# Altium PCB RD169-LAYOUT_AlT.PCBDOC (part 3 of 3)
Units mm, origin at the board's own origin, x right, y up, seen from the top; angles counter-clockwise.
Board outline 192 x 135 mm, 2 copper layers (TOP, BOTTOM), stack 0 mm thick; 266 components, 140 nets, 1304 pads, 0 vias.
Unrouted connection lines stored in the file: 1.
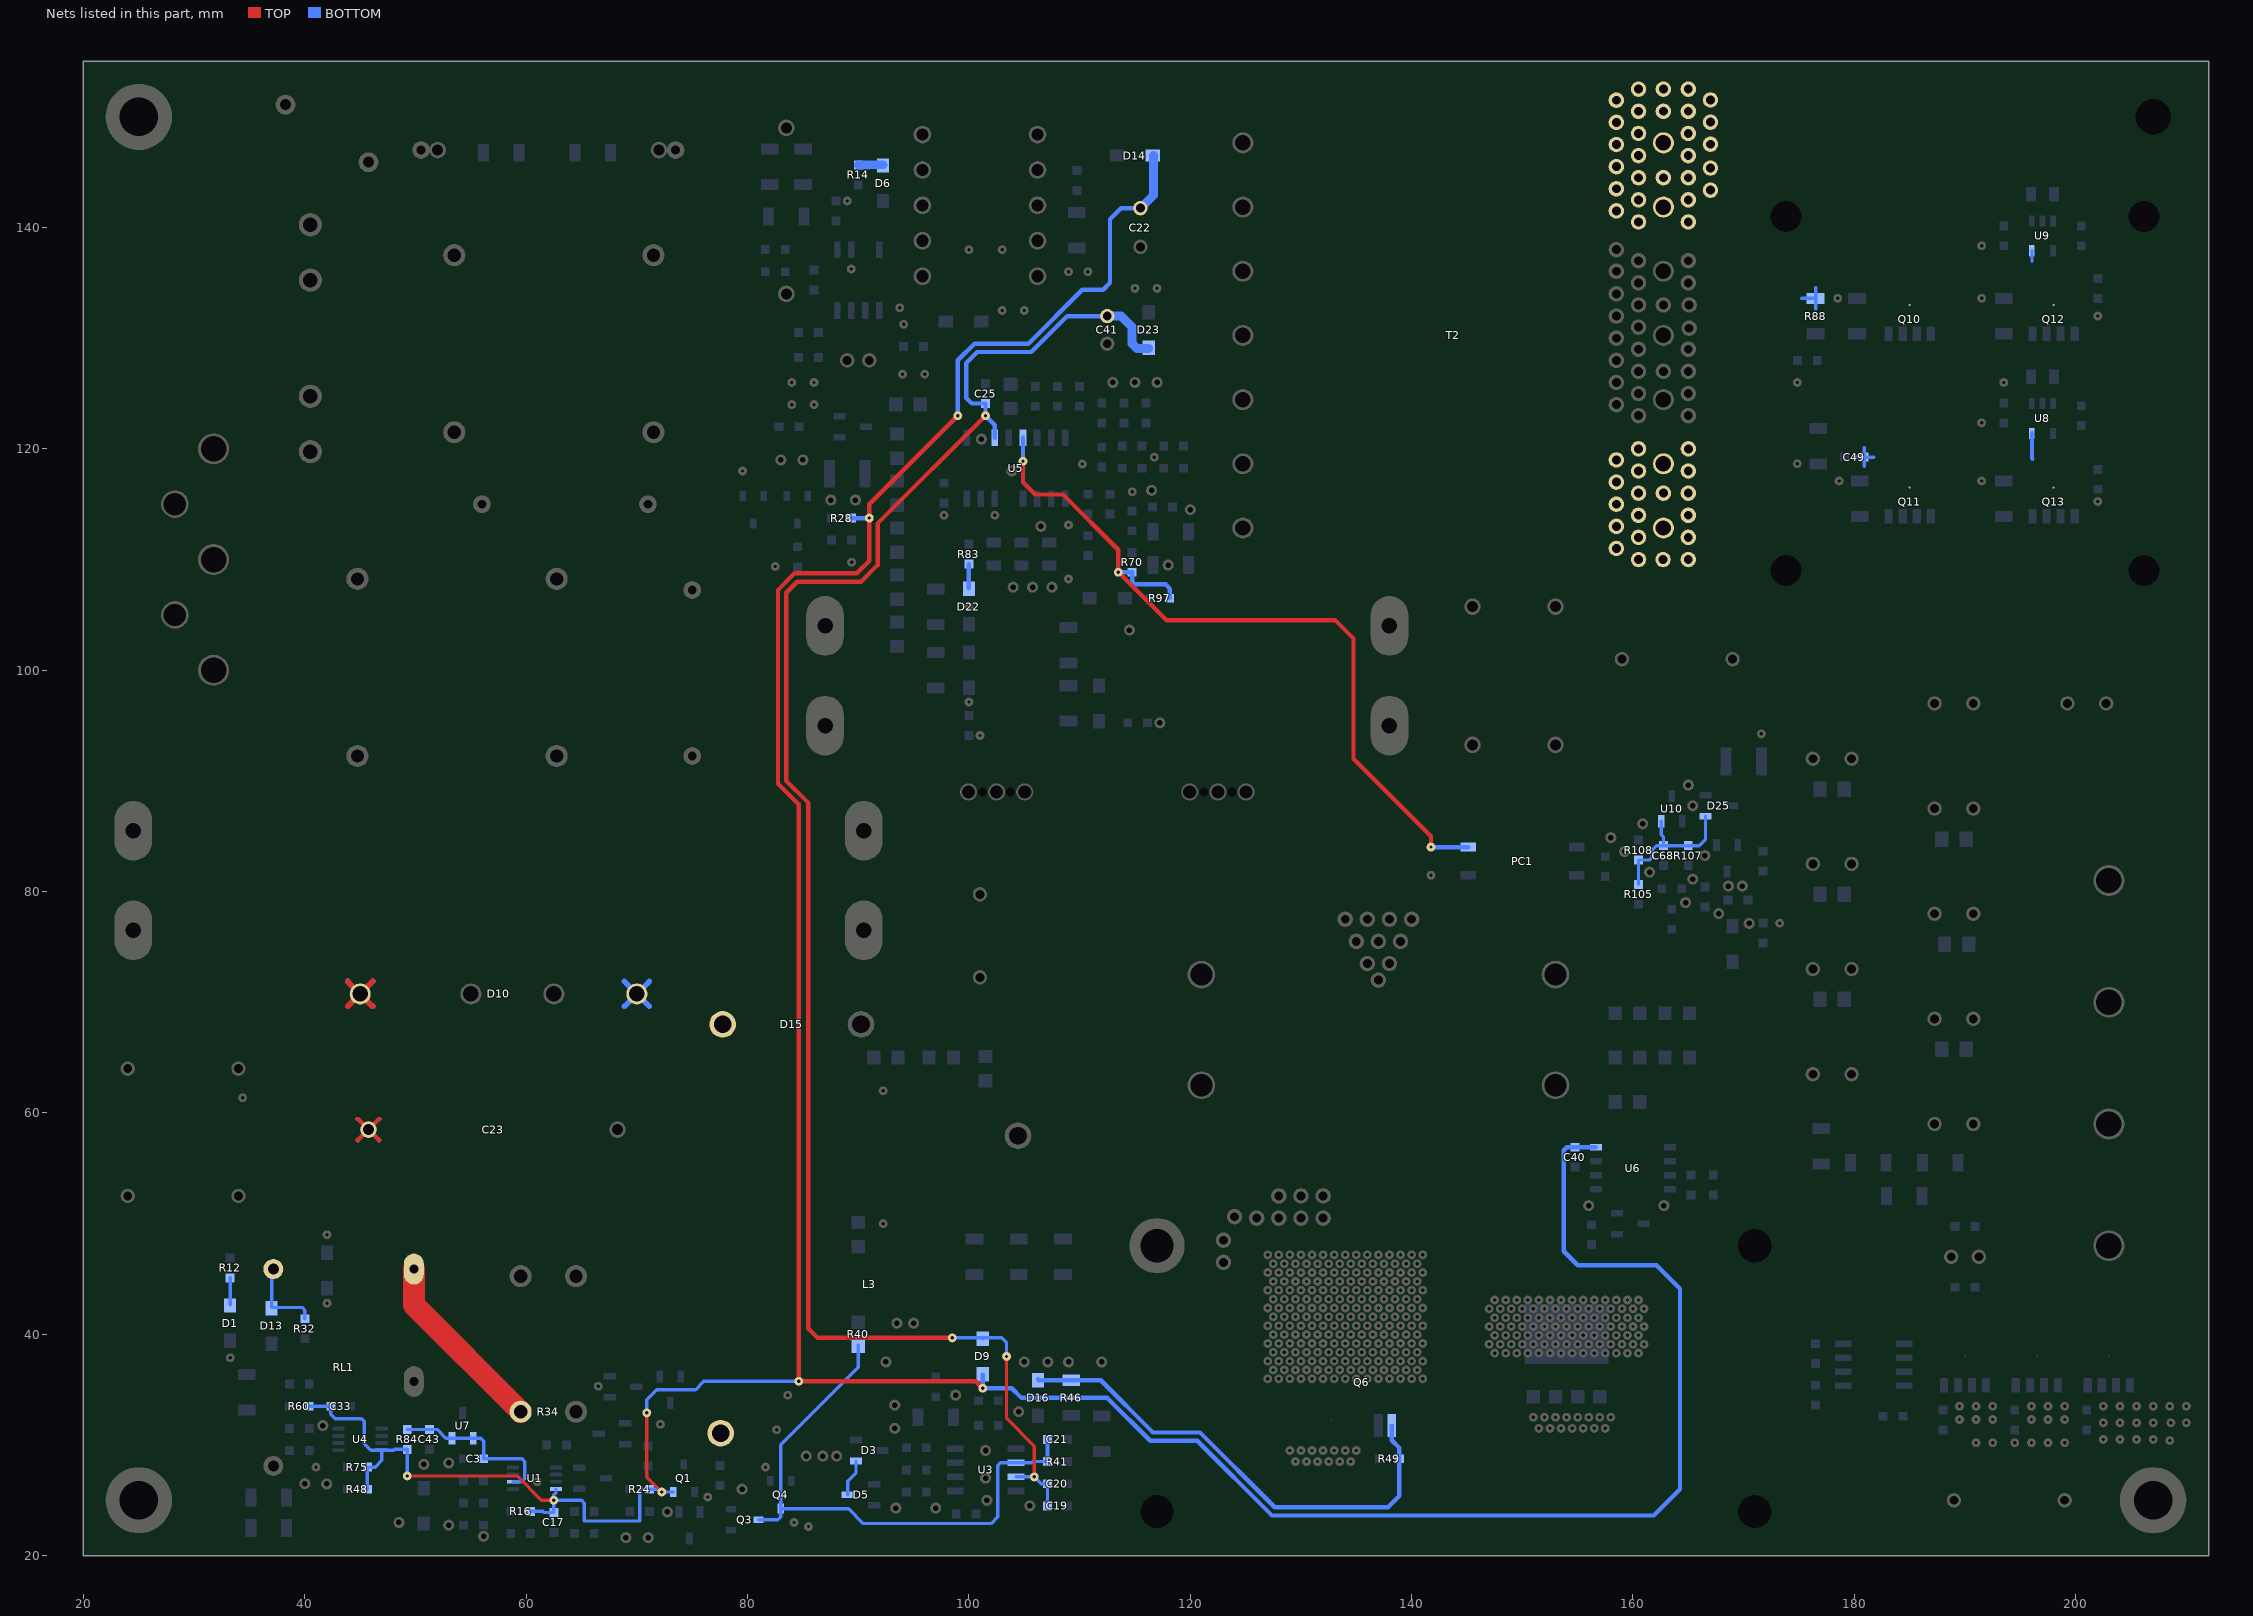
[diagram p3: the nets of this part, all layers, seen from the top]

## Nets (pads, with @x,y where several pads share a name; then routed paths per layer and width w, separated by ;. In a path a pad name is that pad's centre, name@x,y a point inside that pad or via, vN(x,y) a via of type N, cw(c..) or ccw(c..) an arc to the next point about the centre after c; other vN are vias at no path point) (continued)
SIG490: D3.C D5.A | length 3.4
  BOTTOM w0.3: D5.A@89.05,25.5 89.05,26.725 89.8,27.475 D3.C@89.8,28.55
SIG491: C68.2 D25.C R105.2 R107.2 R108.1 U10.2 | length 13.8
  BOTTOM w0.3: R105.2@160.5,80.65 R108.1@160.5,82.85 161.482,82.85 161.75,83.118 161.75,83.775 162.125,84.15 C68.2@162.75,84.15 ; U10.2@162.55,86.35 162.55,85.15 162.75,84.95 C68.2@162.75,84.15 ; D25.C@166.55,86.8 166.55,84.7 166,84.15 R107.2@165,84.15 C68.2@162.75,84.15
SIG508: pad.@104.885,118.875 pad.@113.5,108.85 pad.@141.75,84.02 PC1.C R70.1 R97.1 U5.5 | length 72.6
  TOP w0.4: pad.@104.885,118.875 104.885,116.99 106,115.875 108.5,115.875 113.5,110.875 pad.@113.5,108.85 113.525,108.85 117.875,104.5 133.125,104.5 134.75,102.875 134.75,92 141.75,85 pad.@141.75,84.02
  BOTTOM w0.4: pad.@104.885,118.875 U5.5@104.885,121 ; pad.@113.5,108.85 R70.1@114.75,108.85 114.75,108 115,107.75 117.775,107.75 118.15,107.375 R97.1@118.15,106.5 ; pad.@141.75,84.02 PC1.C@145.1,84.02
SIG519: D13.C R32.1 RL1.1 | length 7.5
  BOTTOM w0.3: RL1.1@37.025,46.015 37,45.99 37,42.425 39.75,42.425 40,42.175 R32.1@40,41.4
SIG520: D1.A R12.2 | length 2.4
  BOTTOM w0.3: D1.A@33.25,42.675 R12.2@33.25,45.1
SIG521: D6.C R14.2 | length 2.3
  BOTTOM w0.8: R14.2@90,145.65 90.875,145.65 90.9,145.675 D6.C@92.25,145.675
SIG522: D22.A R83.1 | length 2.2
  BOTTOM w0.4: D22.A@100,107.425 R83.1@100,109.6
SIG529: D16.A Q6.1 R46.2 R49.2 | length 44.5
  BOTTOM w0.4: D16.A@106.25,35.925 106.325,35.85 R46.2@109.25,35.85 111.904,35.85 116.629,31.125 120.875,31.125 127.625,24.375 137.875,24.375 138.9,25.4 R49.2@138.9,28.75 138.9,29.725 138.2,30.425 Q6.1@138.2,31.76
SIG535: D10.4 R34.2 RL1.4 | length 23.3
  TOP w2: RL1.4@49.85,45.89 49.85,42.65 R34.2@59.5,33
  BOTTOM w0.5: 68.869,69.619 D10.4@70,70.75 ; 68.869,71.881 D10.4@70,70.75 ; 71.131,69.619 D10.4@70,70.75 ; 71.131,71.881 D10.4@70,70.75
SIG536: C23.1 D10.1 D15.A L3.1 | length 23.6
  TOP w0.4: 44.795,57.545 C23.1@45.75,58.5 ; 44.795,59.455 C23.1@45.75,58.5 ; 46.705,57.545 C23.1@45.75,58.5 ; 46.705,59.455 C23.1@45.75,58.5
  TOP w0.5: 43.869,69.619 D10.1@45,70.75 ; 43.869,71.881 D10.1@45,70.75 ; 46.131,69.619 D10.1@45,70.75 ; 46.131,71.881 D10.1@45,70.75
  BOTTOM w0.4: 44.795,57.545 C23.1@45.75,58.5 ; 44.795,59.455 C23.1@45.75,58.5 ; 46.705,57.545 C23.1@45.75,58.5 ; 46.705,59.455 C23.1@45.75,58.5
  BOTTOM w0.5: 43.869,69.619 D10.1@45,70.75 ; 43.869,71.881 D10.1@45,70.75 ; 46.131,69.619 D10.1@45,70.75 ; 46.131,71.881 D10.1@45,70.75
U8_5: C49.2 pad.@158.5,111 pad.@158.5,113 pad.@158.5,115 pad.@158.5,117 pad.@158.5,119 pad.@160.5,110 pad.@160.5,112 pad.@160.5,114 pad.@160.5,116 pad.@160.5,118 pad.@160.5,120 pad.@162.75,116 pad.@162.716,109.999 pad.@165,110 pad.@165,112 pad.@165,114 pad.@165,116 pad.@165,118 pad.@165.01,119.995 Q11.5 Q13.5 T2.8 T2.9 U8.5 | length 5.7
  BOTTOM w0.3: 180.05,119.25 C49.2@180.9,119.25 ; 180.9,118.4 C49.2@180.9,119.25 ; 180.9,120.1 C49.2@180.9,119.25 ; 181.75,119.25 C49.2@180.9,119.25
  BOTTOM w0.4: U8.5@196.05,121.4 196.05,119.145 196.095,119.1
U9_5: pad.@158.5,141.5 pad.@158.5,143.5 pad.@158.5,145.5 pad.@158.5,147.5 pad.@158.5,149.5 pad.@158.5,151.5 pad.@160.5,140.5 pad.@160.5,142.5 pad.@160.5,144.5 pad.@160.5,146.5 pad.@160.5,148.5 pad.@160.5,150.5 pad.@160.5,152.5 pad.@162.75,144.5 pad.@162.75,150.5 pad.@162.75,152.5 pad.@165,140.5 pad.@165,142.5 pad.@165,144.5 pad.@165,146.5 pad.@165,148.5 pad.@165,150.5 pad.@165,152.5 pad.@167,143.375 pad.@167,145.375 pad.@167,147.525 pad.@167,149.525 pad.@167,151.525 Q10.5 Q12.5 R88.1 T2.13 T2.14 U9.5 | length 4.1
  BOTTOM w0.3: 175.25,133.6 R88.1@176.5,133.6 ; 176.5,132.65 R88.1@176.5,133.6 ; 176.5,134.55 R88.1@176.5,133.6 ; 196.05,136.95 U9.5@196.05,137.9
VCC-IC: C19.1 C20.1 C25.1 C41.2 D9.C D23.C pad.@98.5,39.675 pad.@101.5,123 pad.@103.4,38 pad.@105.9,27.115 U3.7 U5.3 | length 159.8
  TOP w0.3: pad.@103.4,38 103.4,32.4 105.9,29.9 pad.@105.9,27.115
  TOP w0.4: pad.@98.5,39.675 86.325,39.675 85.5,40.5 85.5,88 83.5,90 83.5,107 84.5,108 90.25,108 91.75,109.5 91.75,113.25 pad.@101.5,123
  BOTTOM w0.3: pad.@98.5,39.675 101.175,39.675 D9.C@101.25,39.6 101.325,39.675 102.975,39.675 103.4,39.25 pad.@103.4,38 ; U3.7@104.25,27.115 pad.@105.9,27.115 106.515,26.5 C20.1@107.1,26.5 C19.1@107.1,24.5
  BOTTOM w0.4: U5.3@102.345,121 102.345,122.155 pad.@101.5,123 C25.1@101.5,124.1 100.25,124.1 99.75,124.6 99.75,127.75 100.75,128.75 105.625,128.75 108.875,132 C41.2@112.5,132
  BOTTOM w0.8: C41.2@112.5,132 113.75,132 114.75,131 114.75,129.5 115.175,129.075 D23.C@116.25,129.075
VCC_P1: C17.1 C22.2 C33.1 C40.1 D9.A D14.C pad.@49.25,27.2 pad.@62.5,25 pad.@70.9,32.9 pad.@72.25,25.75 pad.@84.625,35.75 pad.@91,113.75 pad.@99,123 pad.@101.25,35.125 Q1.E R16.1 R24.1 R28.1 R48.1 R60.1 R75.1 R84.1 U1.8 U4.8 U6.8 | length 340.8
  TOP w0.3: pad.@49.25,27.2 59.175,27.2 61.375,25 pad.@62.5,25 ; pad.@70.9,32.9 70.9,27.1 pad.@72.25,25.75
  TOP w0.4: pad.@99,123 91,115 pad.@91,113.75 91,109.875 89.875,108.75 84.25,108.75 82.75,107.25 82.75,89.75 84.625,87.875 pad.@84.625,35.75 100.625,35.75 pad.@101.25,35.125
  BOTTOM w0.3: R60.1@40.4,33.5 C33.1@42.35,33.5 42.35,32.775 42.75,32.375 45.125,32.375 45.375,32.125 45.375,30.125 45.975,29.525 U4.8@46.95,29.525 ; R48.1@45.65,26 R75.1@45.65,28 46.35,28 46.95,28.6 U4.8@46.95,29.525 ; pad.@49.25,27.2 R84.1@49.25,29.6 48.125,29.6 48.05,29.525 U4.8@46.95,29.525 ; R16.1@60.4,24 61.5,24 61.6,23.9 C17.1@62.5,23.9 pad.@62.5,25 ; U1.8@62.7,26.025 62.7,25.7 62.5,25.5 pad.@62.5,25 ; pad.@70.9,32.9 70.9,34.1 71.8,35 75.3,35 76.05,35.75 pad.@84.625,35.75 ; Q1.E@73.3,25.75 pad.@72.25,25.75 72,26 R24.1@71.15,26 70.25,26 70.25,23.125 65.25,23.125 65.25,24.75 65,25 pad.@62.5,25 ; C40.1@154.75,56.9 C40.1@154.755,56.905
  BOTTOM w0.4: R28.1@89.4,113.75 pad.@91,113.75 ; pad.@99,123 99,128 100.5,129.5 105.375,129.5 110.25,134.375 112.125,134.375 112.75,135 112.75,140.75 113.75,141.75 C22.2@115.5,141.75 ; D9.A@101.25,36.325 pad.@101.25,35.125 103.875,35.125 104.75,34.25 112.5,34.25 116.375,30.375 120.625,30.375 127.375,23.625 161.875,23.625 164.25,26 164.25,44.125 162.125,46.25 155,46.25 153.75,47.5 153.75,56.625 154.025,56.9 C40.1@154.75,56.9 156.645,56.9 U6.8@156.65,56.905
  BOTTOM w0.8: C22.2@115.5,141.75 116.675,142.925 D14.C@116.675,146.5
Vref: C3.1 C43.1 R84.2 U1.2 U7.1 U7.2 | length 15.5
  BOTTOM w0.3: R84.2@49.25,31.4 C43.1@51.25,31.4 51.95,31.4 52.75,30.6 U7.2@53.3,30.6 U7.1@55.2,30.6 55.9,30.6 56.15,30.35 C3.1@56.15,28.75 59.625,28.75 59.875,28.5 59.875,26.925 59.625,26.675 U1.2@58.8,26.675
VSENSE: C21.1 Q3.C Q4.C R40.2 R41.1 U3.6 | length 52.2
  BOTTOM w0.3: Q3.C@81,23.25 82.75,23.25 83,23.5 Q4.C@83,24.25 ; R40.2@90,39 90,37 83,30 Q4.C@83,24.25 ; R41.1@107.1,28.5 105.75,28.5 105.635,28.385 U3.6@104.25,28.385 102.85,28.385 102.6,28.135 102.6,23.5 102,22.9 90.475,22.9 89.125,24.25 Q4.C@83,24.25
  BOTTOM w0.4: R41.1@107.1,28.5 C21.1@107.1,30.5
pads on no net: D3.NC D4.NC D5.NC D7.NC D11.NC D12.NC D17.NC D18.1 D18.2 D19.NC D24.NC D25.NC D26.NC HS1.3T HS1.4T HS2.2T HS2.3T HS2.4T HS3.1T HS3.2T HS3.3T HS3.4T T1.2 T1.6 T1.8 T1.10 T2.3 T2.5 T2.7 TB1.1T TB1.2T U4.7

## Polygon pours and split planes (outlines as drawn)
SIG536 on TOP "TOP1" (solid, pour order 46): 66 vertices, not listed, extent 43,29 79.5,72.5
GND_PRI_S on TOP "TOP2" (solid, pour order 47): 1613 vertices, not listed, extent 34.5,21 175,64.5
+HV on TOP "TOP3" (solid, pour order 48): 147,37 146,38 146,47 147,48 165,48 166,47 166,38 165,37
SIG231 on TOP "TOP4" (solid, pour order 49): 19 vertices, not listed, extent 126,28 166,48.25
GND_PRI_P on TOP "TOP5" (solid, pour order 50): 134 vertices, not listed, extent 85,28.1 141,107
U9_5 on TOP "TOP6" (solid, pour order 51): 158,139.5 157.5,140 157.5,153 158.5,154 167.2,154 168.2,153 168.2,142.7 165,139.5
GND_SEC on TOP "TOP7" (solid, pour order 52): 41 vertices, not listed, extent 156.5,76.125 171.5,90.75
U8_5 on TOP "TOP8" (solid, pour order 53): 160.5,108 157.5,111 157.5,120.5 158,121 166,121 167,120 167,109 166,108
ISNS_VCR on TOP "TOP9" (solid, pour order 54): 17 vertices, not listed, extent 122.8,103.5 155.25,121.2
GND_PRI_P on TOP "TOP10" (solid, pour order 55): 17 vertices, not listed, extent 136,91 160.5,107
12VREC on TOP "TOP11" (solid, pour order 56): 170 vertices, not listed, extent 157.5,29.5 211,154
GND_PRI_P on TOP "TOP12" (solid, pour order 57): 82,134.938 cw(c82.15,134.938) 82.044,135.044 82.456,135.456 cw(c82.562,135.35) 82.562,135.5 82.971,135.5 cw(c82.971,135.35) 83.026,135.21 ccw(c83.5,134) 82.29,134.474 cw(c82.15,134.529) 82,134.529
GND_PRI_P on TOP "TOP13" (solid, pour order 58): 337 vertices, not listed, extent 82,121.75 127,150.5
GND_PRI_P on TOP "TOP14" (solid, pour order 59): 826 vertices, not listed, extent 82,102 121.5,133
FG3 on BOTTOM "BOTTOM15" (solid, pour order 2): 21.5,21 21,21.5 21,65.5 21.5,66 25.25,66 26,65.25 26,50.5 24.25,48.75 24.25,30.25 28.5,26 28.5,21.5 28,21
SIG536 on BOTTOM "BOTTOM16" (solid, pour order 3): 43.6,55.9 43,56.5 43,72.75 43.5,73.25 47,73.25 47.5,72.75 47.5,56.4 47,55.9
SIG535 on BOTTOM "BOTTOM17" (solid, pour order 4): 30 vertices, not listed, extent 48.3,43.6 72,73.25
ISENSE on BOTTOM "BOTTOM18" (solid, pour order 5): 34 vertices, not listed, extent 48.6,34.3 112,60
SIG232 on BOTTOM "BOTTOM19" (solid, pour order 6): 20 vertices, not listed, extent 29.5,116.5 42.5,127.5
SIG242 on BOTTOM "BOTTOM20" (solid, pour order 7): 35 vertices, not listed, extent 29.5,107.5 56.75,148.625
SIG237 on BOTTOM "BOTTOM21" (solid, pour order 8): 27 vertices, not listed, extent 36,133.5 75.125,154
SIG219 on BOTTOM "BOTTOM22" (solid, pour order 9): 61.7,106.6 61.1,107.2 61.1,109.1 61.6,109.6 62.3,109.6 66.5,113.8 66.5,123.5 67.2,124.2 71.5,124.2 72.5,123.2 72.5,114.3 64.8,106.6
SIG239 on BOTTOM "BOTTOM23" (solid, pour order 10): 44.1,106.7 43.5,107.3 43.5,109.5 44,110 46.125,110 51.5,115.375 51.5,123.2 52.8,124.5 57,124.5 58.1,123.4 58.1,114.6 50.2,106.7
FG2 on BOTTOM "BOTTOM24" (solid, pour order 11): 17 vertices, not listed, extent 21,97.5 34.003,154
GND_PRI_P on BOTTOM "BOTTOM25" (solid, pour order 12): 89,73.5 88.5,74 88.5,87.625 85,91.125 85,97.475 85.5,97.975 88.5,97.975 89,97.475 89,91.875 92.5,88.375 92.5,74 92,73.5
HS on BOTTOM "BOTTOM26" (solid, pour order 13): 53 vertices, not listed, extent 104.19,83.125 132.5,132.5
12VREC on BOTTOM "BOTTOM27" (solid, pour order 14): 158,122 157.5,122.5 157.5,138.2 158.05,138.75 165.45,138.75 166,138.2 166,122.5 165.5,122
GND_PRI_P on BOTTOM "BOTTOM28" (solid, pour order 15): 97 vertices, not listed, extent 109.083,131.379 118.8,142.7
GND_PRI_P on BOTTOM "BOTTOM29" (solid, pour order 16): 76 vertices, not listed, extent 118.5,70.375 160.3,144.25
+HV on BOTTOM "BOTTOM30" (solid, pour order 17): 38 vertices, not listed, extent 97.5,37.25 162,89.7
SIG231 on BOTTOM "BOTTOM31" (solid, pour order 18): 32 vertices, not listed, extent 102.75,25 162.5,59.5
GND_PRI_P on BOTTOM "BOTTOM32" (solid, pour order 19): 27 vertices, not listed, extent 98,27.5 136.2,53.5
GND_PRI_S on BOTTOM "BOTTOM33" (solid, pour order 20): 180 vertices, not listed, extent 103.1,23.5 110.334,34.625
GND_PRI_S on BOTTOM "BOTTOM34" (solid, pour order 21): 174 vertices, not listed, extent 77.95,22 89.863,29.75
GND_PRI_S on BOTTOM "BOTTOM35" (solid, pour order 22): 420 vertices, not listed, extent 56.6,21 77.272,26.593
FG1 on BOTTOM "BOTTOM36" (solid, pour order 23): 197.5,21 197,21.5 197,27.5 197.5,28 210.5,28 211,27.5 211,22 210,21
U9_5 on BOTTOM "BOTTOM37" (solid, pour order 24): 166 vertices, not listed, extent 157.5,132 201.125,154
SIG441 on BOTTOM "BOTTOM38" (solid, pour order 25): 145 vertices, not listed, extent 182,37 211,64.5
12VREC on BOTTOM "BOTTOM39" (solid, pour order 26): 156 vertices, not listed, extent 181,29 211,36.875
U8_5 on BOTTOM "BOTTOM40" (solid, pour order 27): 61 vertices, not listed, extent 157.5,108 201.2,122.5
GND_PRI_P on BOTTOM "BOTTOM41" (solid, pour order 28): 123 vertices, not listed, extent 97.345,120.2 101.745,124.001
GND_PRI_P on BOTTOM "BOTTOM42" (solid, pour order 29): 92.375,115.8 92.375,116.2 94.625,116.2 94.625,115.8
GND_PRI_P on BOTTOM "BOTTOM43" (solid, pour order 30): 70 vertices, not listed, extent 80.95,114.5 92.8,120
GND_PRI_P on BOTTOM "BOTTOM44" (solid, pour order 31): 111.1,119.05 111.1,119.45 112.9,119.45 112.9,119.05
GND_PRI_P on BOTTOM "BOTTOM45" (solid, pour order 32): 111.915,114.8 111.915,115.2 113.65,115.2 113.65,114.8
GND_PRI_P on BOTTOM "BOTTOM46" (solid, pour order 33): 369 vertices, not listed, extent 94.2,114.5 113.445,121.055
GND_PRI_P on BOTTOM "BOTTOM47" (solid, pour order 34): 763 vertices, not listed, extent 100.875,102.5 121,130.75
GND_PRI_P on BOTTOM "BOTTOM48" (solid, pour order 35): 306 vertices, not listed, extent 100.25,122.05 117.75,130.75
GND_PRI_P on BOTTOM "BOTTOM49" (solid, pour order 36): 217 vertices, not listed, extent 80.5,123 112.25,139.7
GND_PRI_S on BOTTOM "BOTTOM50" (solid, pour order 37): 75 vertices, not listed, extent 161.45,45.6 168.375,56
GND_PRI_S on BOTTOM "BOTTOM51" (solid, pour order 38): 173 vertices, not listed, extent 154.25,46.75 164.4,58.25
GND_SEC on BOTTOM "BOTTOM52" (solid, pour order 39): 349 vertices, not listed, extent 157.375,82.334 168.5,90.75
GND_SEC on BOTTOM "BOTTOM53" (solid, pour order 40): 181 vertices, not listed, extent 160.95,77.95 167.298,82.782
GND_SEC on BOTTOM "BOTTOM54" (solid, pour order 41): 1067 vertices, not listed, extent 162.2,21 211,146
GND_PRI_S on BOTTOM "BOTTOM55" (solid, pour order 42): 1007 vertices, not listed, extent 35.875,21.7 63.846,40.25
GND_PRI_S on BOTTOM "BOTTOM56" (solid, pour order 43): 1003 vertices, not listed, extent 83.45,23.35 137.4,42
SIG222 on BOTTOM "BOTTOM57" (solid, pour order 44): 27 vertices, not listed, extent 58.5,68.25 76.6,95.3
SIG226 on BOTTOM "BOTTOM58" (solid, pour order 45): 67 vertices, not listed, extent 32.5,60.75 76.9,109.2
no net on Top Solder "TOPSOLDER59" (solid, pour order 0): 126.707,35.5 126.5,35.707 126.5,47.543 126.707,47.75 141.293,47.75 141.5,47.543 141.5,35.707 141.293,35.5
no net on Top Solder "TOPSOLDER60" (solid, pour order 0): 161.5,37.707 161.293,37.5 147.207,37.5 146.5,38.207 146.5,43.293 147.207,44 161.293,44 161.5,43.793
no net on Top Solder "TOPSOLDER61" (solid, pour order 0): 155.707,117.5 144.793,117.5 143.5,118.793 143.5,141.707 144.793,143 155.707,143 157,141.707 157,118.793
no net on Bottom Solder "BOTTOMSOLDER62" (solid, pour order 0): 126.707,35.5 126.5,35.707 126.5,47.543 126.707,47.75 141.293,47.75 141.5,47.543 141.5,35.707 141.293,35.5
no net on Bottom Solder "BOTTOMSOLDER63" (solid, pour order 0): 161.5,37.707 161.293,37.5 147.207,37.5 146.5,38.207 146.5,43.293 147.207,44 161.293,44 161.5,43.793
no net on Bottom Solder "BOTTOMSOLDER64" (solid, pour order 0): 155.707,117.5 144.793,117.5 143.5,118.793 143.5,141.707 144.793,143 155.707,143 157,141.707 157,118.793
no net on Top Overlay "TOPOVERLAY65" (solid, pour order 0): 116.055,128.609 cw(c112.5,130.75) 114.641,127.195 113.867,128.48 ccw(c112.5,130.75) 114.77,129.383
no net on Top Overlay "TOPOVERLAY66" (solid, pour order 0): 192.141,50.555 cw(c190,47) 193.555,49.141 192.27,48.367 ccw(c190,47) 191.367,49.27
no net on Top Overlay "TOPOVERLAY67" (solid, pour order 0): 191.757,63.171 cw(c189,59) 193.171,61.757 191.92,60.93 ccw(c189,59) 190.93,61.92
no net on Top Overlay "TOPOVERLAY68" (solid, pour order 0): 175.243,87.829 cw(c178,92) 173.829,89.243 175.08,90.07 ccw(c178,92) 176.07,89.08
no net on Top Overlay "TOPOVERLAY69" (solid, pour order 0): 175.243,78.329 cw(c178,82.5) 173.829,79.743 175.08,80.57 ccw(c178,82.5) 176.07,79.58
no net on Top Overlay "TOPOVERLAY70" (solid, pour order 0): 175.243,68.829 cw(c178,73) 173.829,70.243 175.08,71.07 ccw(c178,73) 176.07,70.08
no net on Top Overlay "TOPOVERLAY71" (solid, pour order 0): 175.243,59.329 cw(c178,63.5) 173.829,60.743 175.08,61.57 ccw(c178,63.5) 176.07,60.58
no net on Top Overlay "TOPOVERLAY72" (solid, pour order 0): 191.757,101.171 cw(c189,97) 193.171,99.757 191.92,98.93 ccw(c189,97) 190.93,99.92
no net on Top Overlay "TOPOVERLAY73" (solid, pour order 0): 191.757,91.671 cw(c189,87.5) 193.171,90.257 191.92,89.43 ccw(c189,87.5) 190.93,90.42
no net on Top Overlay "TOPOVERLAY74" (solid, pour order 0): 191.757,82.171 cw(c189,78) 193.171,80.757 191.92,79.93 ccw(c189,78) 190.93,80.92
no net on Top Overlay "TOPOVERLAY75" (solid, pour order 0): 191.757,72.671 cw(c189,68.5) 193.171,71.257 191.92,70.43 ccw(c189,68.5) 190.93,71.42
no net on Top Overlay "TOPOVERLAY76" (solid, pour order 0): 88.335,124.921 cw(c90,128) 86.921,126.335 88.241,127.049 ccw(c90,128) 89.049,126.241
no net on Top Overlay "TOPOVERLAY77" (solid, pour order 0): 119.671,137.243 cw(c115.5,140) 118.257,135.829 117.43,137.08 ccw(c115.5,140) 118.42,138.07
no net on Top Overlay "TOPOVERLAY78" (solid, pour order 0): 203.757,101.171 cw(c201,97) 205.171,99.757 203.92,98.93 ccw(c201,97) 202.93,99.92
no net on Top Overlay "TOPOVERLAY79" (solid, pour order 0): 143.408,78.374 ccw(c153,67.5) 142.126,77.092 141.001,78.084 cw(c153,67.5) 142.416,79.499
no net on Top Overlay "TOPOVERLAY80" (solid, pour order 0): 111.408,78.374 ccw(c121,67.5) 110.126,77.092 109.001,78.084 cw(c121,67.5) 110.416,79.499
no net on Top Overlay "TOPOVERLAY81" (solid, pour order 0): 86,70.2 87,70.2 87,65.8 86,65.8
no net on Top Overlay "TOPOVERLAY82" (solid, pour order 0): 83.2,67.05 83.2,68.95 84.7,68
no net on Top Overlay "TOPOVERLAY83" (solid, pour order 0): 94,149.75 cw(c94,149.5) 94,149.25 cw(c94,149.5) 94,149.75
no net on Top Overlay "TOPOVERLAY84" (solid, pour order 0): 177.209,149.078 177.209,152.152 177.209,154.171 192.137,154.171 192.137,149.078
no net on Top Overlay "TOPOVERLAY85" (solid, pour order 0): 151 vertices, not listed, extent 181.07,151.145 181.713,152.108
no net on Top Overlay "TOPOVERLAY86" (solid, pour order 0): 35 vertices, not listed, extent 187.592,151.81 188.064,152.087
no net on Top Overlay "TOPOVERLAY87" (solid, pour order 0): 39 vertices, not listed, extent 187.592,151.166 188.085,151.475
no net on Top Overlay "TOPOVERLAY88" (solid, pour order 0): 189.57,152.055 189.74,151.47 189.398,151.47 189.567,152.055
no net on Top Overlay "TOPOVERLAY89" (solid, pour order 0): 107.5,91.92 107.456,90.92 97.544,90.92 97.5,91.92
no net on Top Overlay "TOPOVERLAY90" (solid, pour order 0): 127.5,91.92 127.456,90.92 117.544,90.92 117.5,91.92
no net on Top Overlay "TOPOVERLAY91" (solid, pour order 0): 45,25.325 cw(c44.75,25.325) 44.5,25.325 cw(c44.75,25.325) 45,25.325
no net on Top Overlay "TOPOVERLAY92" (solid, pour order 0): 141.5,57.108 cw(c153,67.5) 141.5,77.892
no net on Top Overlay "TOPOVERLAY93" (solid, pour order 0): 119.5,53.207 120.32,54.027 ccw(c121,62.5) 129.497,62.719 129.5,62.625 129.5,80.515 cw(c120.9,67.5) 119.5,51.963
no net on Top Overlay "TOPOVERLAY94" (solid, pour order 0): 176.766,52.394 176.766,52.046 175.69,52.046 175.69,52.394
no net on Top Overlay "TOPOVERLAY95" (solid, pour order 0): 177.48,51.135 177.232,51.376 178.101,52.22 177.232,53.063 177.48,53.304 178.598,52.22
no net on Top Overlay "TOPOVERLAY96" (solid, pour order 0): 55 vertices, not listed, extent 179.189,50.921 180.844,53.679
no net on Top Overlay "TOPOVERLAY97" (solid, pour order 0): 182.787,52.554 182.787,52.233 181.724,52.233 181.724,51.255 182.98,51.255 182.98,50.934 181.366,50.934 181.366,53.666 182.911,53.666 182.911,53.345 181.724,53.345 181.724,52.554
no net on Top Overlay "TOPOVERLAY98" (solid, pour order 0): 48 vertices, not listed, extent 183.503,50.894 185.31,53.706
no net on Top Overlay "TOPOVERLAY99" (solid, pour order 0): 18 vertices, not listed, extent 165.029,53.409 166.643,56.141
no net on Top Overlay "TOPOVERLAY100" (solid, pour order 0): 21 vertices, not listed, extent 167.166,53.409 169.029,56.141
no net on Top Overlay "TOPOVERLAY101" (solid, pour order 0): 169.965,56.141 169.965,53.409 169.606,53.409 169.606,56.141
no net on Top Overlay "TOPOVERLAY102" (solid, pour order 0): 171.716,53.61 170.599,54.695 171.716,55.779 171.964,55.538 171.095,54.695 171.964,53.851
no net on Top Overlay "TOPOVERLAY103" (solid, pour order 0): 173.521,54.869 173.521,54.521 172.444,54.521 172.444,54.869
no net on Top Overlay "TOPOVERLAY104" (solid, pour order 0): 21 vertices, not listed, extent 32.021,128.923 32.967,129.569
no net on Top Overlay "TOPOVERLAY105" (solid, pour order 0): 32.425,130.307 32.53,130.307 32.53,129.923 32.868,129.923 32.868,130.359 32.973,130.359 32.973,129.814 32.027,129.814 32.027,130.336 32.132,130.336 32.132,129.923 32.425,129.923
no net on Top Overlay "TOPOVERLAY106" (solid, pour order 0): 18 vertices, not listed, extent 32.027,130.647 32.973,131.264
no net on Top Overlay "TOPOVERLAY107" (solid, pour order 0): 32.973,131.566 32.027,131.566 32.027,131.675 32.868,131.675 32.868,132.112 32.973,132.112
no net on Top Overlay "TOPOVERLAY108" (solid, pour order 0): 32.973,132.29 32.016,132.613 32.016,132.661 32.016,132.708 32.973,133.031 32.973,132.917 32.685,132.817 32.685,132.504 32.973,132.404
no net on Top Overlay "TOPOVERLAY109" (solid, pour order 0): 49 vertices, not listed, extent 32.016,133.261 32.984,133.94
no net on Top Overlay "TOPOVERLAY110" (solid, pour order 0): 32.425,134.727 32.53,134.727 32.53,134.342 32.868,134.342 32.868,134.779 32.973,134.779 32.973,134.233 32.027,134.233 32.027,134.755 32.132,134.755 32.132,134.342 32.425,134.342
no net on Top Overlay "TOPOVERLAY111" (solid, pour order 0): 23 vertices, not listed, extent 32.016,135.432 32.979,136.144
no net on Top Overlay "TOPOVERLAY112" (solid, pour order 0): 32.973,137.063 32.973,136.944 32.226,136.564 32.973,136.564 32.973,136.455 32.027,136.455 32.027,136.574 32.774,136.954 32.027,136.954 32.027,137.063
no net on Top Overlay "TOPOVERLAY113" (solid, pour order 0): 32.973,137.393 32.027,137.393 32.027,137.502 32.868,137.502 32.868,137.939 32.973,137.939
no net on Top Overlay "TOPOVERLAY114" (solid, pour order 0): 32.027,138.806 32.552,138.516 32.973,138.516 32.973,138.407 32.552,138.407 32.027,138.113 32.027,138.226 32.458,138.459 32.027,138.691
no net on Top Overlay "TOPOVERLAY115" (solid, pour order 0): 32.729,140 32.027,140.128 32.027,140.232 32.984,140.052 32.984,139.957 32.215,139.791 32.984,139.625 32.984,139.53 32.027,139.35 32.027,139.454 32.729,139.582 32.027,139.739 32.027,139.843
no net on Top Overlay "TOPOVERLAY116" (solid, pour order 0): 32.027,140.648 32.149,140.648 32.149,140.596 32.851,140.596 32.851,140.648 32.973,140.648 32.973,140.435 32.851,140.435 32.851,140.487 32.149,140.487 32.149,140.435 32.027,140.435
no net on Top Overlay "TOPOVERLAY117" (solid, pour order 0): 32.132,141.254 32.973,141.254 32.973,141.145 32.132,141.145 32.132,140.874 32.027,140.874 32.027,141.525 32.132,141.525
no net on Top Overlay "TOPOVERLAY118" (solid, pour order 0): 32.027,142.401 32.973,142.401 32.973,142.291 32.53,142.291 32.53,141.902 32.973,141.902 32.973,141.793 32.027,141.793 32.027,141.902 32.425,141.902 32.425,142.291 32.027,142.291
no net on Top Overlay "TOPOVERLAY119" (solid, pour order 0): 80 vertices, not listed, extent 32.016,143.077 32.984,143.68
no net on Top Overlay "TOPOVERLAY120" (solid, pour order 0): 32.973,143.901 32.016,144.224 32.016,144.272 32.016,144.319 32.973,144.642 32.973,144.528 32.685,144.428 32.685,144.115 32.973,144.015
no net on Top Overlay "TOPOVERLAY121" (solid, pour order 0): 32.973,145.622 32.973,145.513 32.248,145.513 32.973,145.295 32.973,145.219 32.248,145.001 32.973,145.001 32.973,144.892 32.027,144.892 32.027,145.039 32.763,145.257 32.027,145.475 32.027,145.622
no net on Top Overlay "TOPOVERLAY122" (solid, pour order 0): 32.425,146.433 32.53,146.433 32.53,146.048 32.868,146.048 32.868,146.485 32.973,146.485 32.973,145.939 32.027,145.939 32.027,146.461 32.132,146.461 32.132,146.048 32.425,146.048
no net on Top Overlay "TOPOVERLAY123" (solid, pour order 0): 32.132,147.48 32.973,147.48 32.973,147.371 32.132,147.371 32.132,147.1 32.027,147.1 32.027,147.751 32.132,147.751
no net on Top Overlay "TOPOVERLAY124" (solid, pour order 0): 32.027,148.636 32.552,148.346 32.973,148.346 32.973,148.237 32.552,148.237 32.027,147.943 32.027,148.057 32.458,148.29 32.027,148.522
no net on Top Overlay "TOPOVERLAY125" (solid, pour order 0): 18 vertices, not listed, extent 32.027,148.876 32.973,149.493
no net on Top Overlay "TOPOVERLAY126" (solid, pour order 0): 32.425,150.275 32.53,150.275 32.53,149.89 32.868,149.89 32.868,150.327 32.973,150.327 32.973,149.781 32.027,149.781 32.027,150.303 32.132,150.303 32.132,149.89 32.425,149.89
no net on Top Overlay "TOPOVERLAY127" (solid, pour order 0): 28.817,127.964 28.922,127.964 28.922,127.622 29.348,127.622 29.348,127.513 28.402,127.513 28.402,128.059 28.507,128.059 28.507,127.622 28.817,127.622
no net on Top Overlay "TOPOVERLAY128" (solid, pour order 0): 23 vertices, not listed, extent 28.391,128.309 29.354,129.021
no net on Top Overlay "TOPOVERLAY129" (solid, pour order 0): 21 vertices, not listed, extent 28.396,129.346 29.342,129.992
no net on Top Overlay "TOPOVERLAY130" (solid, pour order 0): 49 vertices, not listed, extent 28.391,130.593 29.359,131.271
no net on Top Overlay "TOPOVERLAY131" (solid, pour order 0): 23 vertices, not listed, extent 28.391,131.555 29.354,132.267
no net on Top Overlay "TOPOVERLAY132" (solid, pour order 0): 29.348,133.185 29.348,133.067 28.601,132.687 29.348,132.687 29.348,132.578 28.402,132.578 28.402,132.696 29.149,133.076 28.402,133.076 28.402,133.185
no net on Top Overlay "TOPOVERLAY133" (solid, pour order 0): 28.507,133.833 29.348,133.833 29.348,133.724 28.507,133.724 28.507,133.454 28.402,133.454 28.402,134.104 28.507,134.104
no net on Top Overlay "TOPOVERLAY134" (solid, pour order 0): 28.402,134.543 28.524,134.543 28.524,134.491 29.226,134.491 29.226,134.543 29.348,134.543 29.348,134.33 29.226,134.33 29.226,134.382 28.524,134.382 28.524,134.33 28.402,134.33
no net on Top Overlay "TOPOVERLAY135" (solid, pour order 0): 29.348,135.429 29.348,135.31 28.601,134.93 29.348,134.93 29.348,134.821 28.402,134.821 28.402,134.94 29.149,135.32 28.402,135.32 28.402,135.429
no net on Top Overlay "TOPOVERLAY136" (solid, pour order 0): 27 vertices, not listed, extent 28.402,135.75 29.359,136.357
no net on Top Overlay "TOPOVERLAY137" (solid, pour order 0): 28.8,137.167 28.905,137.167 28.905,136.782 29.243,136.782 29.243,137.219 29.348,137.219 29.348,136.673 28.402,136.673 28.402,137.195 28.507,137.195 28.507,136.782 28.8,136.782
no net on Top Overlay "TOPOVERLAY138" (solid, pour order 0): 28.402,137.511 28.402,137.621 28.402,137.796 28.402,137.891 28.441,137.972 28.518,138.038 28.6,138.108 28.721,138.143 29.038,138.143 29.158,138.107 29.243,138.034 29.313,137.973 29.348,137.894 29.348,137.796 29.348,137.511
no net on Top Overlay "TOPOVERLAY139" (solid, pour order 0): 18 vertices, not listed, extent 28.402,138.815 29.348,139.432
no net on Top Overlay "TOPOVERLAY140" (solid, pour order 0): 21 vertices, not listed, extent 28.396,139.739 29.342,140.384
no net on Top Overlay "TOPOVERLAY141" (solid, pour order 0): 23 vertices, not listed, extent 28.391,140.62 29.354,141.332
no net on Top Overlay "TOPOVERLAY142" (solid, pour order 0): 28.507,141.97 29.348,141.97 29.348,141.861 28.507,141.861 28.507,141.59 28.402,141.59 28.402,142.241 28.507,142.241
no net on Top Overlay "TOPOVERLAY143" (solid, pour order 0): 28.8,142.998 28.905,142.998 28.905,142.614 29.243,142.614 29.243,143.05 29.348,143.05 29.348,142.505 28.402,142.505 28.402,143.027 28.507,143.027 28.507,142.614 28.8,142.614
no net on Top Overlay "TOPOVERLAY144" (solid, pour order 0): 49 vertices, not listed, extent 28.391,143.329 29.359,144.007
no net on Top Overlay "TOPOVERLAY145" (solid, pour order 0): 28.507,144.632 29.348,144.632 29.348,144.523 28.507,144.523 28.507,144.252 28.402,144.252 28.402,144.903 28.507,144.903
no net on Top Overlay "TOPOVERLAY146" (solid, pour order 0): 28.402,145.342 28.524,145.342 28.524,145.29 29.226,145.29 29.226,145.342 29.348,145.342 29.348,145.129 29.226,145.129 29.226,145.181 28.524,145.181 28.524,145.129 28.402,145.129
no net on Top Overlay "TOPOVERLAY147" (solid, pour order 0): 23 vertices, not listed, extent 28.391,145.606 29.354,146.318
no net on Top Overlay "TOPOVERLAY148" (solid, pour order 0): 29.348,147.237 29.348,147.118 28.601,146.738 29.348,146.738 29.348,146.629 28.402,146.629 28.402,146.748 29.149,147.128 28.402,147.128 28.402,147.237
no net on Top Overlay "TOPOVERLAY149" (solid, pour order 0): 48 vertices, not listed, extent 23.125,126.977 26.875,129.387
no net on Top Overlay "TOPOVERLAY150" (solid, pour order 0): 26.821,130.034 23.179,131.119 23.179,131.376 23.179,131.634 26.821,132.719 26.821,132.203 25.732,131.854 25.732,130.898 26.821,130.548
no net on Top Overlay "TOPOVERLAY151" (solid, pour order 0): 26 vertices, not listed, extent 23.179,133.438 26.857,135.664
no net on Top Overlay "TOPOVERLAY152" (solid, pour order 0): 23.607,137.67 26.821,137.67 26.821,137.192 23.607,137.192 23.607,136.383 23.179,136.383 23.179,138.48 23.607,138.48
no net on Top Overlay "TOPOVERLAY153" (solid, pour order 0): 23.179,139.678 26.821,139.678 26.821,139.2 23.179,139.2
no net on Top Overlay "TOPOVERLAY154" (solid, pour order 0): 22 vertices, not listed, extent 23.143,140.326 26.857,142.9
no net on Top Overlay "TOPOVERLAY155" (solid, pour order 0): 26.821,145.773 26.821,145.294 24.214,144.025 26.821,144.025 26.821,143.547 23.179,143.547 23.179,144.025 25.786,145.294 23.179,145.294 23.179,145.773
no net on Top Overlay "TOPOVERLAY156" (solid, pour order 0): 31.029,127.412 30.072,127.735 30.072,127.782 30.072,127.83 31.029,128.153 31.029,128.039 30.741,127.939 30.741,127.626 31.029,127.526
no net on Top Overlay "TOPOVERLAY157" (solid, pour order 0): 52 vertices, not listed, extent 30.072,128.393 31.04,129.072
no net on Top Overlay "TOPOVERLAY158" (solid, pour order 0): 31.029,129.307 30.072,129.63 30.072,129.678 30.072,129.725 31.029,130.048 31.029,129.934 30.741,129.834 30.741,129.521 31.029,129.421
no net on Top Overlay "TOPOVERLAY159" (solid, pour order 0): 30.083,130.468 30.205,130.468 30.205,130.416 30.907,130.416 30.907,130.468 31.029,130.468 31.029,130.255 30.907,130.255 30.907,130.307 30.205,130.307 30.205,130.255 30.083,130.255
no net on Top Overlay "TOPOVERLAY160" (solid, pour order 0): 31.029,131.354 31.029,131.235 30.282,130.855 31.029,130.855 31.029,130.746 30.083,130.746 30.083,130.865 30.83,131.245 30.083,131.245 30.083,131.354
no net on Top Overlay "TOPOVERLAY161" (solid, pour order 0): 80 vertices, not listed, extent 30.072,131.66 31.04,132.263
no net on Top Overlay "TOPOVERLAY162" (solid, pour order 0): 30.188,132.883 31.029,132.883 31.029,132.774 30.188,132.774 30.188,132.503 30.083,132.503 30.083,133.154 30.188,133.154
no net on Top Overlay "TOPOVERLAY163" (solid, pour order 0): 21 vertices, not listed, extent 30.078,133.807 31.023,134.452
no net on Top Overlay "TOPOVERLAY164" (solid, pour order 0): 30.083,134.873 30.205,134.873 30.205,134.82 30.907,134.82 30.907,134.873 31.029,134.873 31.029,134.659 30.907,134.659 30.907,134.711 30.205,134.711 30.205,134.659 30.083,134.659
no net on Top Overlay "TOPOVERLAY165" (solid, pour order 0): 80 vertices, not listed, extent 30.072,135.136 31.04,135.739
no net on Top Overlay "TOPOVERLAY166" (solid, pour order 0): 30.459,136.326 31.029,136.653 31.029,136.525 30.548,136.25 30.675,136.141 31.029,136.141 31.029,136.032 30.083,136.032 30.083,136.141 30.514,136.141 30.083,136.511 30.083,136.649
no net on Top Overlay "TOPOVERLAY167" (solid, pour order 0): 23 vertices, not listed, extent 30.072,137.264 31.035,137.976
no net on Top Overlay "TOPOVERLAY168" (solid, pour order 0): 30.498,138.748 30.603,138.748 30.603,138.406 31.029,138.406 31.029,138.297 30.083,138.297 30.083,138.843 30.188,138.843 30.188,138.406 30.498,138.406
no net on Top Overlay "TOPOVERLAY169" (solid, pour order 0): 30.498,139.938 30.603,139.938 30.603,139.596 31.029,139.596 31.029,139.486 30.083,139.486 30.083,140.032 30.188,140.032 30.188,139.596 30.498,139.596
no net on Top Overlay "TOPOVERLAY170" (solid, pour order 0): 30.083,140.467 30.205,140.467 30.205,140.415 30.907,140.415 30.907,140.467 31.029,140.467 31.029,140.254 30.907,140.254 30.907,140.306 30.205,140.306 30.205,140.254 30.083,140.254
no net on Top Overlay "TOPOVERLAY171" (solid, pour order 0): 21 vertices, not listed, extent 30.078,140.76 31.023,141.405
no net on Top Overlay "TOPOVERLAY172" (solid, pour order 0): 30.481,142.144 30.586,142.144 30.586,141.759 30.924,141.759 30.924,142.196 31.029,142.196 31.029,141.65 30.083,141.65 30.083,142.172 30.188,142.172 30.188,141.759 30.481,141.759
no net on Top Overlay "TOPOVERLAY173" (solid, pour order 0): 31.178,142.526 31.178,142.479 31.029,142.526 31.029,142.479 30.907,142.479 30.907,142.588 31.029,142.588
no net on Top Overlay "TOPOVERLAY174" (solid, pour order 0): 34.848,136.968 33.891,137.29 33.891,137.338 33.891,137.385 34.848,137.708 34.848,137.594 34.56,137.494 34.56,137.181 34.848,137.082
no net on Top Overlay "TOPOVERLAY175" (solid, pour order 0): 34.848,138.565 34.848,138.447 34.101,138.067 34.848,138.067 34.848,137.958 33.902,137.958 33.902,138.076 34.649,138.456 33.902,138.456 33.902,138.565
no net on Top Overlay "TOPOVERLAY176" (solid, pour order 0): 33.902,138.881 33.902,138.99 33.902,139.166 33.902,139.261 33.941,139.342 34.018,139.408 34.1,139.478 34.221,139.513 34.538,139.513 34.658,139.476 34.743,139.403 34.813,139.343 34.848,139.264 34.848,139.166 34.848,138.881
no net on Top Overlay "TOPOVERLAY177" (solid, pour order 0): 21 vertices, not listed, extent 33.896,140.209 34.842,140.854
no net on Top Overlay "TOPOVERLAY178" (solid, pour order 0): 34.848,141.032 33.891,141.355 33.891,141.403 33.891,141.45 34.848,141.773 34.848,141.659 34.56,141.559 34.56,141.246 34.848,141.146
no net on Top Overlay "TOPOVERLAY179" (solid, pour order 0): 34.007,142.35 34.848,142.35 34.848,142.241 34.007,142.241 34.007,141.97 33.902,141.97 33.902,142.621 34.007,142.621
no net on Top Overlay "TOPOVERLAY180" (solid, pour order 0): 33.902,143.06 34.024,143.06 34.024,143.008 34.726,143.008 34.726,143.06 34.848,143.06 34.848,142.846 34.726,142.846 34.726,142.899 34.024,142.899 34.024,142.846 33.902,142.846
no net on Top Overlay "TOPOVERLAY181" (solid, pour order 0): 34.848,143.946 34.848,143.827 34.101,143.447 34.848,143.447 34.848,143.338 33.902,143.338 33.902,143.457 34.649,143.837 33.902,143.837 33.902,143.946
no net on Top Overlay "TOPOVERLAY182" (solid, pour order 0): 52 vertices, not listed, extent 33.891,144.257 34.859,144.936
no net on Top Overlay "TOPOVERLAY183" (solid, pour order 0): 34.317,146.073 34.422,146.073 34.422,145.731 34.848,145.731 34.848,145.622 33.902,145.622 33.902,146.168 34.007,146.168 34.007,145.731 34.317,145.731
no net on Top Overlay "TOPOVERLAY184" (solid, pour order 0): 27 vertices, not listed, extent 33.902,146.432 34.859,147.04
no net on Top Overlay "TOPOVERLAY185" (solid, pour order 0): 80 vertices, not listed, extent 33.891,147.346 34.859,147.949
no net on Top Overlay "TOPOVERLAY186" (solid, pour order 0): 34.3,148.73 34.405,148.73 34.405,148.346 34.743,148.346 34.743,148.782 34.848,148.782 34.848,148.237 33.902,148.237 33.902,148.759 34.007,148.759 34.007,148.346 34.3,148.346
no net on Bottom Overlay "BOTTOMOVERLAY187" (solid, pour order 0): 33.95,39.7 33.95,40.2 32.55,40.2 32.55,39.7 31.95,39.7 31.95,40.5 34.55,40.5 34.55,39.7
no net on Bottom Overlay "BOTTOMOVERLAY188" (solid, pour order 0): 42.7,44.45 42.7,44.95 41.3,44.95 41.3,44.45 40.7,44.45 40.7,45.25 43.3,45.25 43.3,44.45
no net on Bottom Overlay "BOTTOMOVERLAY189" (solid, pour order 0): 100.55,39.3 100.55,38.8 101.95,38.8 101.95,39.3 102.55,39.3 102.55,38.5 99.95,38.5 99.95,39.3
no net on Bottom Overlay "BOTTOMOVERLAY190" (solid, pour order 0): 106.95,32.95 106.95,33.45 105.55,33.45 105.55,32.95 104.95,32.95 104.95,33.75 107.55,33.75 107.55,32.95
no net on Bottom Overlay "BOTTOMOVERLAY191" (solid, pour order 0): 97.75,25.1 cw(c97.75,25.3) 97.75,25.5 cw(c97.75,25.3) 97.75,25.1
no net on Bottom Overlay "BOTTOMOVERLAY192" (solid, pour order 0): 36.3,42.05 36.3,41.55 37.7,41.55 37.7,42.05 38.3,42.05 38.3,41.25 35.7,41.25 35.7,42.05
no net on Bottom Overlay "BOTTOMOVERLAY193" (solid, pour order 0): 51.45,23.2 51.45,23.7 50.05,23.7 50.05,23.2 49.45,23.2 49.45,24 52.05,24 52.05,23.2
no net on Bottom Overlay "BOTTOMOVERLAY194" (solid, pour order 0): 205.8,34.5 cw(c205.6,34.5) 205.4,34.5 cw(c205.6,34.5) 205.8,34.5
no net on Bottom Overlay "BOTTOMOVERLAY195" (solid, pour order 0): 199.3,34.5 cw(c199.1,34.5) 198.9,34.5 cw(c199.1,34.5) 199.3,34.5
no net on Bottom Overlay "BOTTOMOVERLAY196" (solid, pour order 0): 192.8,34.5 cw(c192.6,34.5) 192.4,34.5 cw(c192.6,34.5) 192.8,34.5
no net on Bottom Overlay "BOTTOMOVERLAY197" (solid, pour order 0): 178,34.6 cw(c178,34.8) 178,35 cw(c178,34.8) 178,34.6
no net on Bottom Overlay "BOTTOMOVERLAY198" (solid, pour order 0): 164.3,57.85 cw(c164.3,57.6) 164.3,57.35 cw(c164.3,57.6) 164.3,57.85
no net on Bottom Overlay "BOTTOMOVERLAY199" (solid, pour order 0): 91.55,145.3 91.55,144.8 92.95,144.8 92.95,145.3 93.55,145.3 93.55,144.5 90.95,144.5 90.95,145.3
no net on Bottom Overlay "BOTTOMOVERLAY200" (solid, pour order 0): 98.2,130.8 98.7,130.8 98.7,132.2 98.2,132.2 98.2,132.8 99,132.8 99,130.2 98.2,130.2
no net on Bottom Overlay "BOTTOMOVERLAY201" (solid, pour order 0): 116.3,147.2 115.8,147.2 115.8,145.8 116.3,145.8 116.3,145.2 115.5,145.2 115.5,147.8 116.3,147.8
no net on Bottom Overlay "BOTTOMOVERLAY202" (solid, pour order 0): 100.7,104.45 100.7,104.95 99.3,104.95 99.3,104.45 98.7,104.45 98.7,105.25 101.3,105.25 101.3,104.45
no net on Bottom Overlay "BOTTOMOVERLAY203" (solid, pour order 0): 98.95,122.05 cw(c99.2,122.05) 99.45,122.05 cw(c99.2,122.05) 98.95,122.05
no net on Bottom Overlay "BOTTOMOVERLAY204" (solid, pour order 0): 92.65,131.5 cw(c92.45,131.5) 92.25,131.5 cw(c92.45,131.5) 92.65,131.5
no net on Bottom Overlay "BOTTOMOVERLAY205" (solid, pour order 0): 99.3,101.3 99.3,100.8 100.7,100.8 100.7,101.3 101.3,101.3 101.3,100.5 98.7,100.5 98.7,101.3
no net on Bottom Overlay "BOTTOMOVERLAY206" (solid, pour order 0): 111.05,98.3 111.05,97.8 112.45,97.8 112.45,98.3 113.05,98.3 113.05,97.5 110.45,97.5 110.45,98.3
no net on Bottom Overlay "BOTTOMOVERLAY207" (solid, pour order 0): 187.8,129.5 cw(c187.6,129.5) 187.4,129.5 cw(c187.6,129.5) 187.8,129.5
no net on Bottom Overlay "BOTTOMOVERLAY208" (solid, pour order 0): 187.8,113 cw(c187.6,113) 187.4,113 cw(c187.6,113) 187.8,113
no net on Bottom Overlay "BOTTOMOVERLAY209" (solid, pour order 0): 200.8,129.5 cw(c200.6,129.5) 200.4,129.5 cw(c200.6,129.5) 200.8,129.5
no net on Bottom Overlay "BOTTOMOVERLAY210" (solid, pour order 0): 200.8,113 cw(c200.6,113) 200.4,113 cw(c200.6,113) 200.8,113
no net on Bottom Overlay "BOTTOMOVERLAY211" (solid, pour order 0): 195.25,124.85 cw(c195.5,124.85) 195.75,124.85 cw(c195.5,124.85) 195.25,124.85
no net on Bottom Overlay "BOTTOMOVERLAY212" (solid, pour order 0): 195.25,141.35 cw(c195.5,141.35) 195.75,141.35 cw(c195.5,141.35) 195.25,141.35
no net on Bottom Overlay "BOTTOMOVERLAY213" (solid, pour order 0): 111.2,105.8 111.7,105.8 111.7,107.2 111.2,107.2 111.2,107.8 112,107.8 112,105.2 111.2,105.2
no net on Bottom Overlay "BOTTOMOVERLAY214" (solid, pour order 0): 169.7,73.95 169.7,74.45 168.3,74.45 168.3,73.95 167.7,73.95 167.7,74.75 170.3,74.75 170.3,73.95
no net on Bottom Overlay "BOTTOMOVERLAY215" (solid, pour order 0): 116.95,129.45 116.95,129.95 115.55,129.95 115.55,129.45 114.95,129.45 114.95,130.25 117.55,130.25 117.55,129.45
no net on Bottom Overlay "BOTTOMOVERLAY216" (solid, pour order 0): 58.05,25.15 cw(c58.05,25.4) 58.05,25.65 cw(c58.05,25.4) 58.05,25.15
no net on Bottom Overlay "BOTTOMOVERLAY217" (solid, pour order 0): 42.3,28.65 cw(c42.3,28.9) 42.3,29.15 cw(c42.3,28.9) 42.3,28.65
no net on Bottom Overlay "BOTTOMOVERLAY218" (solid, pour order 0): 153.125,83.77 cw(c153.125,84.02) 153.125,84.27 cw(c153.125,84.02) 153.125,83.77
no net on Bottom Overlay "BOTTOMOVERLAY219" (solid, pour order 0): 155.95,84.45 cw(c155.95,84.7) 155.95,84.95 cw(c155.95,84.7) 155.95,84.45

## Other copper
TOP:
  text "PC132-01-00" at 20,15 h0.79
  text "PC132-01-00" at 20,15 h0.79
  text "L1 PATTERN BUHIN" at 39,15 h0.79
  text "L1 PATTERN BUHIN" at 39,15 h0.79
BOTTOM:
  text "L2 PATTERN HANDA" at 190.16,15 h0.79
  text "L2 PATTERN HANDA" at 190.16,15 h0.79
  text "PC132-01-00" at 208.71,15 h0.79
  text "PC132-01-00" at 208.71,15 h0.79

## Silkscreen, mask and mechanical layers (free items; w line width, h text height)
Top Overlay:
  drawing of 3897 lines, arcs and shapes, not listed
  text "PC132-01-00" at 20,14 h0.79
  text "L1 SILK BUHIN" at 39,14 h0.79
Bottom Overlay:
  drawing of 8311 lines, arcs and shapes, not listed
  text "L2 SILK HANDA" at 189.69,14 h0.79
Top Solder:
  text "PC132-01-00" at 20.15,12.85 h0.79
  text "L1 RESIST BUHIN" at 39.05,12.85 h0.79
Bottom Solder:
  text "L2 RESIST HANDA" at 189.17,13 h0.79
  text "PC132-01-00" at 208.71,13 h0.79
